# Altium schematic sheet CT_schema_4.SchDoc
size 454 x 430 mm
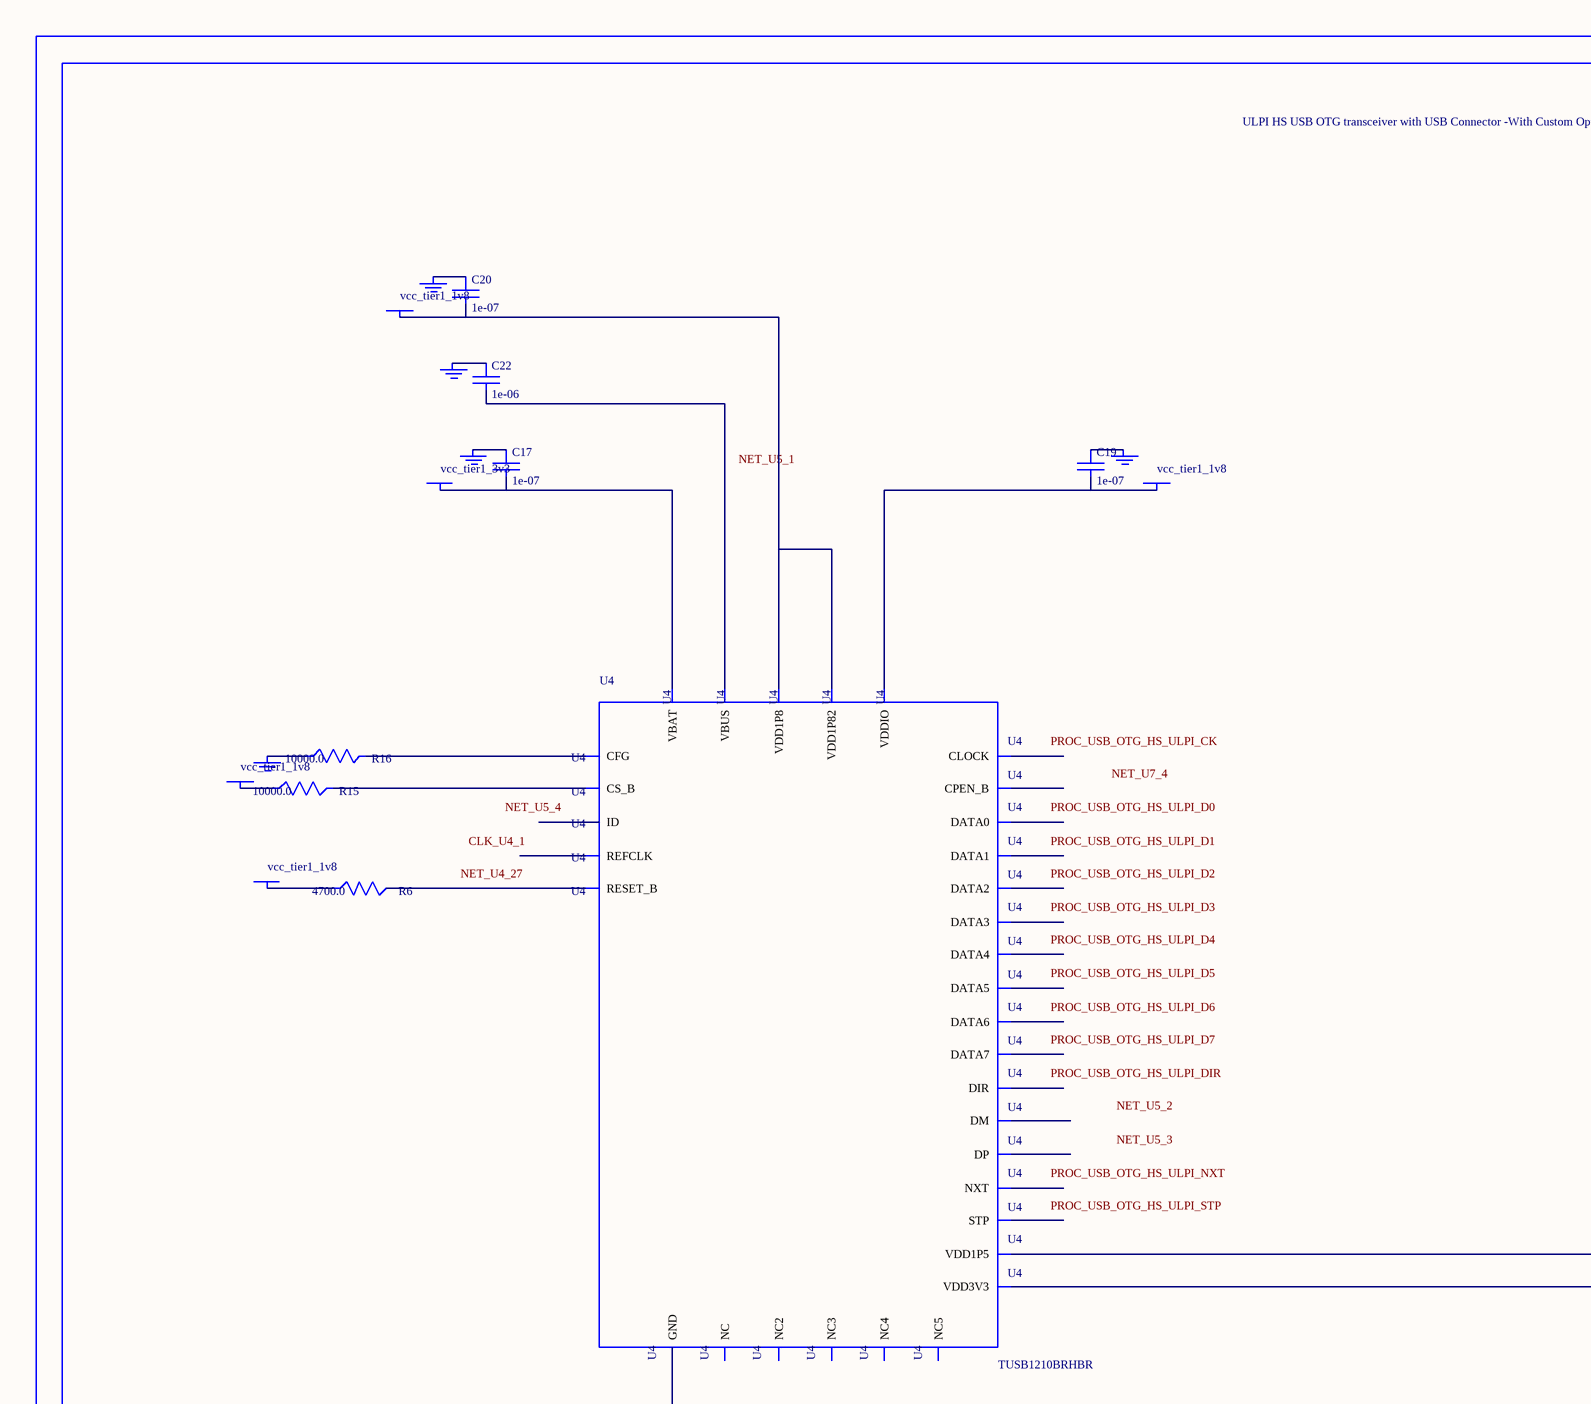
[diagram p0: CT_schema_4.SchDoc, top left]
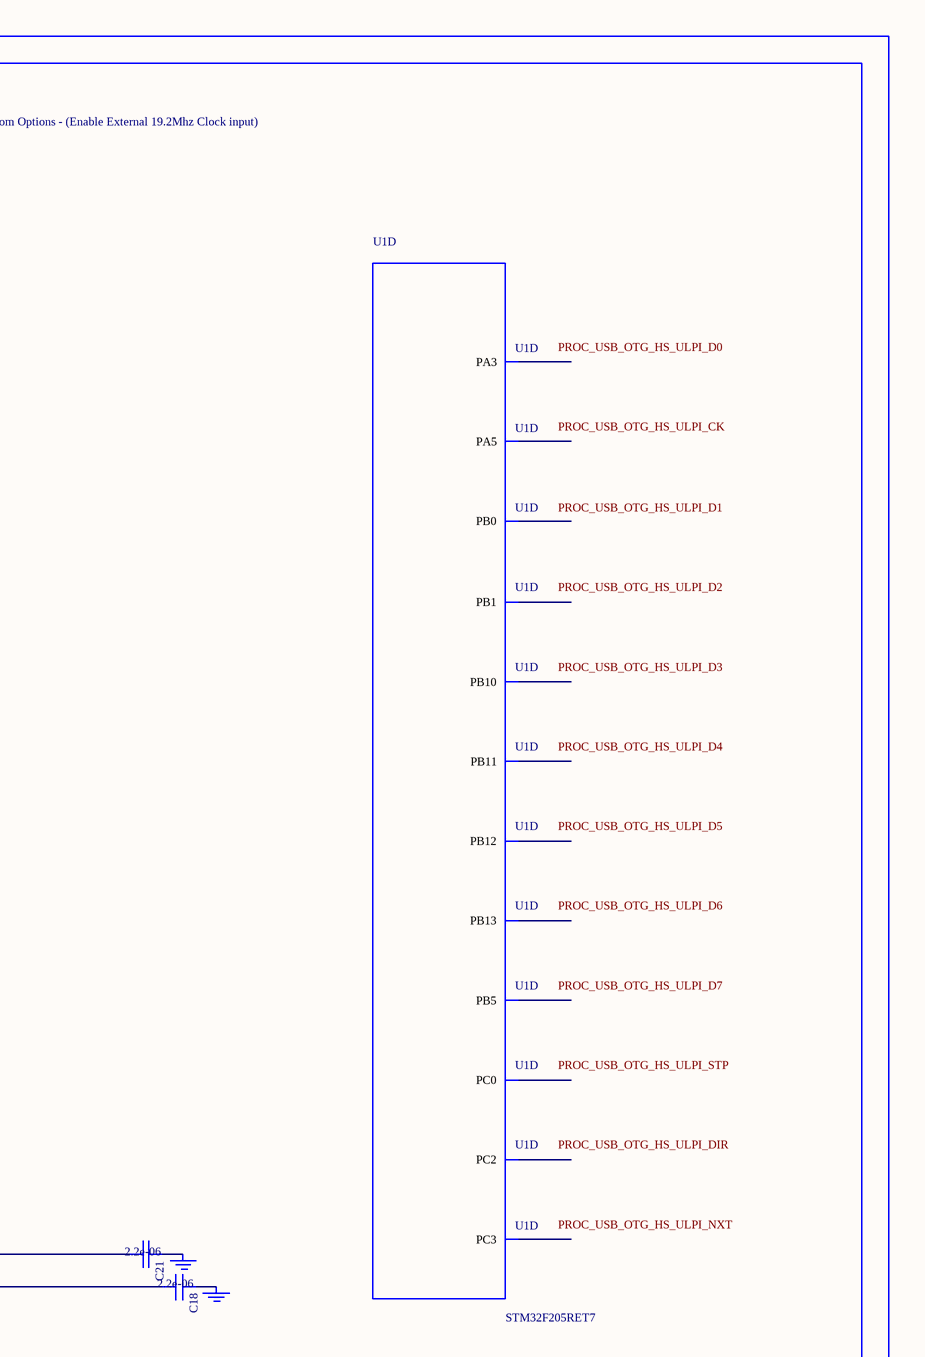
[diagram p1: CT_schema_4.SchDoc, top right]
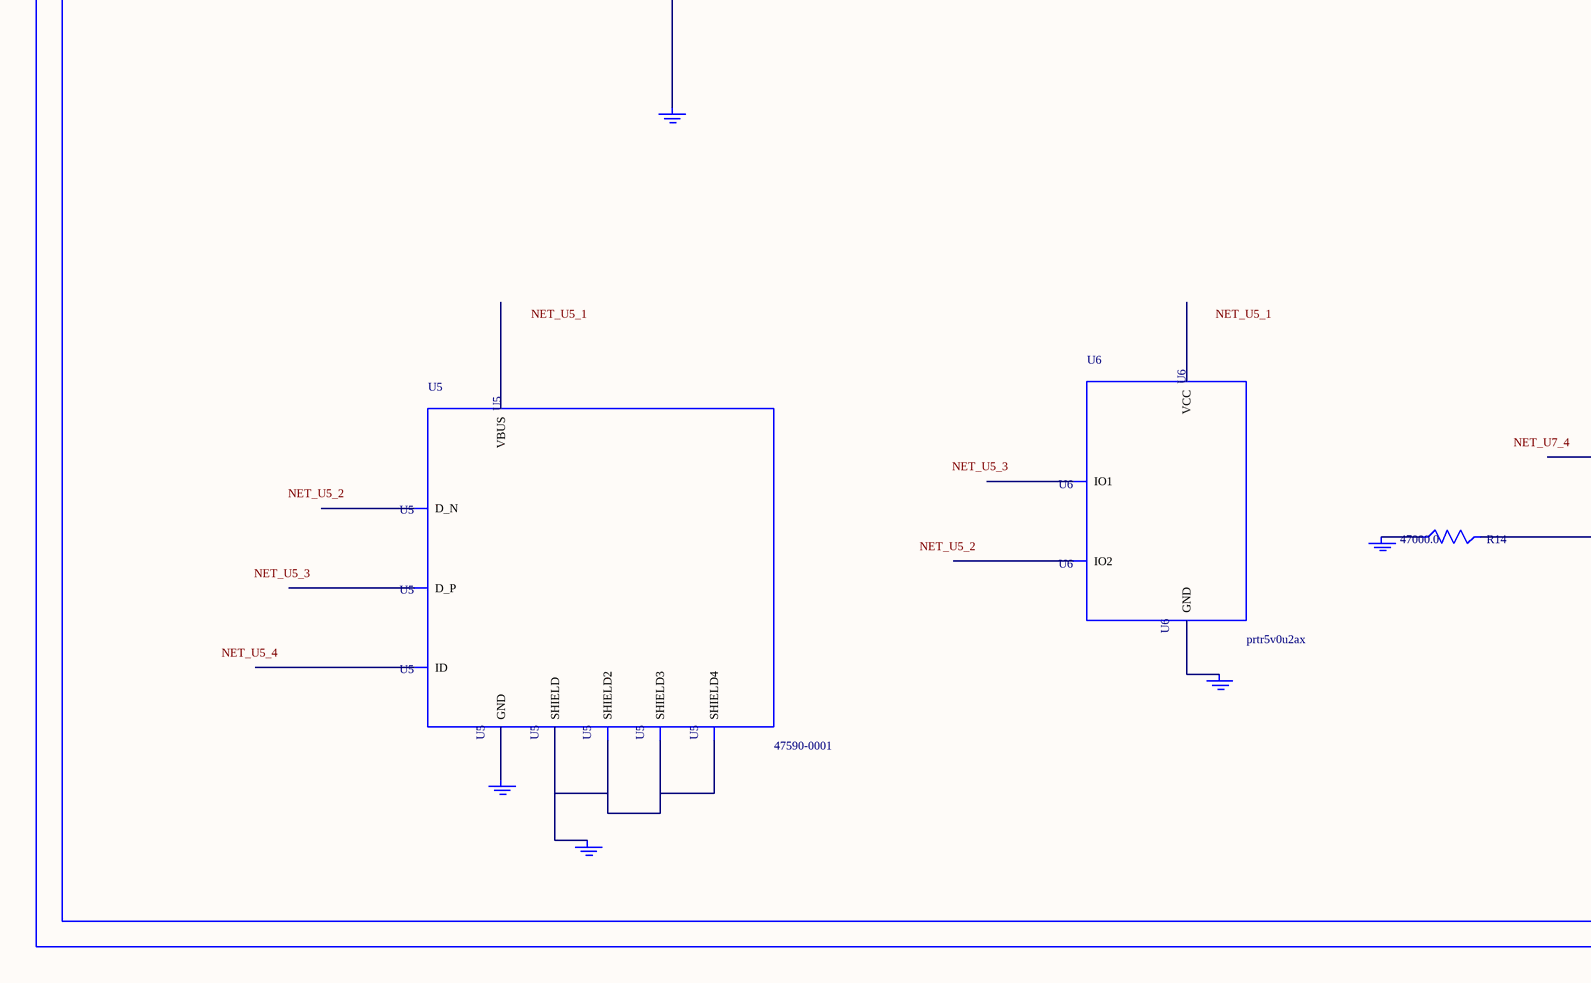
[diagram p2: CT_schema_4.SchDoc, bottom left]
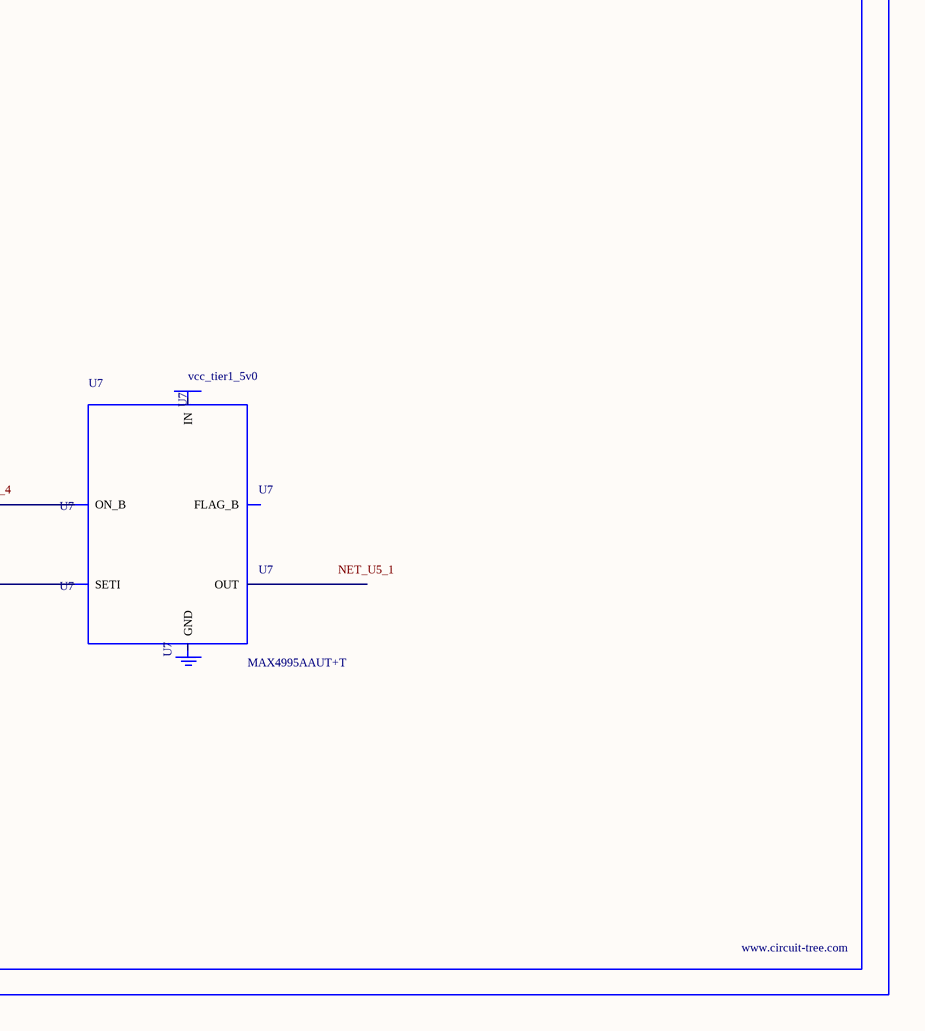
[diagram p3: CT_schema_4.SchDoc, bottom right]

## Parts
BORDER3  (no value)
C17  1e-07  [C0402]
C18  2.2e-06  [C0603]
C19  1e-07  [C0402]
C20  1e-07  [C0402]
C21  2.2e-06  [C0603]
C22  1e-06  [C0603]
GND_INSTANCE_3_0  (no value)
GND_INSTANCE_3_1  (no value)
GND_INSTANCE_3_2  (no value)
GND_INSTANCE_3_3  (no value)
GND_INSTANCE_3_4  (no value)
GND_INSTANCE_3_5  (no value)
GND_INSTANCE_3_6  (no value)
GND_INSTANCE_3_7  (no value)
GND_INSTANCE_3_8  (no value)
GND_INSTANCE_3_9  (no value)
GND_INSTANCE_3_10  (no value)
GND_INSTANCE_3_11  (no value)
GND_INSTANCE_3_12  (no value)
POWER_INSTANCE_3_0  vcc_tier1_1v8
POWER_INSTANCE_3_1  vcc_tier1_3v3
POWER_INSTANCE_3_2  vcc_tier1_1v8
POWER_INSTANCE_3_3  vcc_tier1_1v8
POWER_INSTANCE_3_4  vcc_tier1_1v8
POWER_INSTANCE_3_5  vcc_tier1_5v0
R6  4700.0  [R0603]
R14  47000.0  [R0603]
R15  10000.0  [R0603]
R16  10000.0  [R0603]
U1  STM32F205RET7  [LQFP64]  (part D of 5)
U4  TUSB1210BRHBR  [RHB32_3P45X3P45]
U5  47590-0001  [MICRO_USB_AB]
U6  prtr5v0u2ax  [SOT143B]
U7  MAX4995AAUT+T  [SOT-23-6]

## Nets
NetC17_1: C17.1 GND_INSTANCE_3_3.0(GND)
NetC17_2: C17.2 POWER_INSTANCE_3_1.0(PWR) U4.21(VBAT)
NetC18_1: C18.1 GND_INSTANCE_3_2.0(GND)
NetC18_2: C18.2 U4.20(VDD3V3)
NetC19_1: C19.1 GND_INSTANCE_3_6.0(GND)
NetC19_2: C19.2 POWER_INSTANCE_3_3.0(PWR) U4.32(VDDIO)
NetC20_1: C20.1 GND_INSTANCE_3_5.0(GND)
NetC20_2: C20.2 POWER_INSTANCE_3_2.0(PWR) U4.28(VDD1P8) U4.30(VDD1P82)
NetC21_1: C21.1 GND_INSTANCE_3_0.0(GND)
NetC21_2: C21.2 U4.12(VDD1P5)
NetC22_1: C22.1 GND_INSTANCE_3_4.0(GND)
NetC22_2: C22.2 U4.22(VBUS)
NetGND_INSTANCE_3_1_0: GND_INSTANCE_3_1.0(GND) R16.1
NetGND_INSTANCE_3_7_0: GND_INSTANCE_3_7.0(GND) U4.33(GND)
NetGND_INSTANCE_3_8_0: GND_INSTANCE_3_8.0(GND) U5.6(SHIELD) U5.7(SHIELD2) U5.8(SHIELD3) U5.9(SHIELD4)
NetGND_INSTANCE_3_9_0: GND_INSTANCE_3_9.0(GND) U5.5(GND)
NetGND_INSTANCE_3_10_0: GND_INSTANCE_3_10.0(GND) U6.1(GND)
NetGND_INSTANCE_3_11_0: GND_INSTANCE_3_11.0(GND) R14.1
NetPOWER_INSTANCE_3_0_0: POWER_INSTANCE_3_0.0(PWR) R15.1
NetPOWER_INSTANCE_3_4_0: POWER_INSTANCE_3_4.0(PWR) R6.1
NetR6_2: R6.2 U4.27(RESET_B)
NetR14_2: R14.2 U7.3(SETI)
NetR15_2: R15.2 U4.11(CS_B)
NetR16_2: R16.2 U4.14(CFG)

Not connected (* = marked no-connect by the designer): GND_INSTANCE_3_12 0(GND); POWER_INSTANCE_3_5 0(PWR); U1 8(PC0) 10(PC2) 11(PC3) 17(PA3) 21(PA5) 26(PB0) 27(PB1) 29(PB10) 30(PB11) 33(PB12) 34(PB13) 57(PB5); U4 1(REFCLK) 2(NXT) 3(DATA0) 4(DATA1) 5(DATA2) 6(DATA3) 7(DATA4) 8(NC) 9(DATA5) 10(DATA6) 13(DATA7) 15(NC2) 16(NC3) 17(CPEN_B) 18(DP) 19(DM) 23(ID) 24(NC4) 25(NC5) 26(CLOCK) 29(STP) 31(DIR); U5 1(VBUS) 2(D_N) 3(D_P) 4(ID); U6 2(IO1) 3(IO2) 4(VCC); U7 1(OUT) 2(GND) 4(ON_B) 5(IN) 6(FLAG_B)

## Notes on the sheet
- Labels drawn without touching a wire or pin: CLK_U4_1, NET_U4_27, NET_U5_1, NET_U5_2, NET_U5_3, NET_U5_4, NET_U7_4, PROC_USB_OTG_HS_ULPI_CK, PROC_USB_OTG_HS_ULPI_D0, PROC_USB_OTG_HS_ULPI_D1, PROC_USB_OTG_HS_ULPI_D2, PROC_USB_OTG_HS_ULPI_D3, PROC_USB_OTG_HS_ULPI_D4, PROC_USB_OTG_HS_ULPI_D5, PROC_USB_OTG_HS_ULPI_D6, PROC_USB_OTG_HS_ULPI_D7, PROC_USB_OTG_HS_ULPI_DIR, PROC_USB_OTG_HS_ULPI_NXT, PROC_USB_OTG_HS_ULPI_STP

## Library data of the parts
BORDER3 = BORDER_PAGE3
C17 C19 C20 = C0402C104K3RACTU
C18 C21 = C0603C225K8RACTU
C22 = C0603C105K3RACTU
GND_INSTANCE_3_0-GND_INSTANCE_3_12 = GND
POWER_INSTANCE_3_0-POWER_INSTANCE_3_5 = PWR
R6 = RC0603JR-074K7L
R14 = RC0603JR-0747KL
R15 R16 = RC0603JR-0710KL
